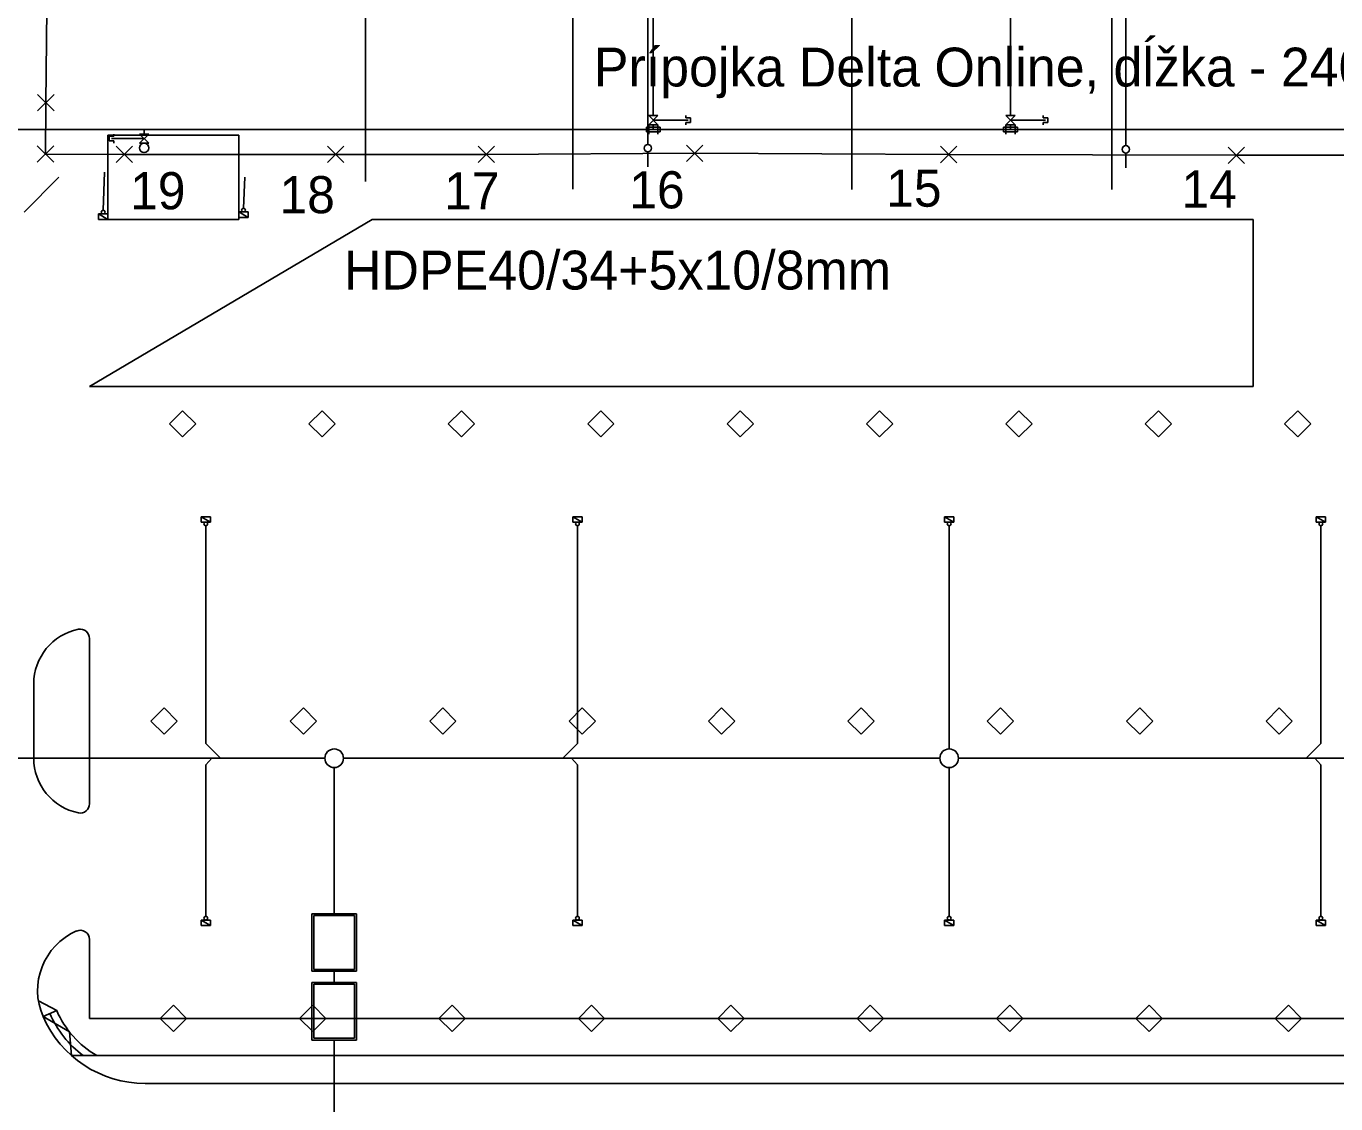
# Model space of a CAD drawing. Extents: x -263995 to -263575, y -1242437 to -1242140.
# Drawn here: x -263920.5 to -263850, y -1242302.6 to -1242244.6 of the extents above; entities that cross this region are included whole.
import ezdxf

# ---------------------------------------------------------------- set-up
doc = ezdxf.new("R2010")
doc.units = 0
for name, color, linetype in [('KFA_2D_SITUACIA_DSP', 7, 'Continuous'), ('KFA_BODY', 7, 'Continuous'), ('KFA_SO_63-3_PRELOZKA_DELTA_ONLINE_TRASA', 7, 'Continuous'), ('POPIS', 7, 'Continuous')]:
    doc.layers.add(name, color=color, linetype=linetype)

msp = doc.modelspace()

# ---------------------------------------------------------------- linework, layer by layer
at = {"layer": 'KFA_2D_SITUACIA_DSP'}
for p, q in [((-263887.043, -1242235.757), (-263887.043, -1242250.954)), ((-263886.743, -1242249.39), (-263886.743, -1242235.757)), ((-263867.518, -1242249.39), (-263867.518, -1242235.757)), ((-263861.318, -1242235.757), (-263861.321, -1242251.015)), ((-263902.238, -1242240.168), (-263902.238, -1242252.949)), ((-263891.068, -1242241.132), (-263891.068, -1242253.353)), ((-263876.068, -1242241.132), (-263876.068, -1242253.37)), ((-263862.068, -1242241.132), (-263862.068, -1242253.368)), ((-263886.493, -1242249.39), (-263886.993, -1242249.39)), ((-263886.993, -1242249.89), (-263886.493, -1242249.39)), ((-263886.993, -1242249.39), (-263886.493, -1242249.89)), ((-263886.493, -1242249.89), (-263886.993, -1242249.89)), ((-263886.993, -1242249.89), (-263886.993, -1242250.39)), ((-263886.743, -1242249.64), (-263884.868, -1242249.64)), ((-263886.743, -1242250.14), (-263886.743, -1242249.89)), ((-263886.743, -1242249.89), (-263886.743, -1242250.14)), ((-263886.493, -1242249.89), (-263886.493, -1242250.39)), ((-263884.993, -1242249.515), (-263884.993, -1242249.39)), ((-263884.743, -1242249.515), (-263884.993, -1242249.515)), ((-263884.993, -1242249.765), (-263884.993, -1242249.89)), ((-263884.993, -1242249.765), (-263884.743, -1242249.765)), ((-263884.743, -1242249.765), (-263884.743, -1242249.515)), ((-263867.268, -1242249.39), (-263867.768, -1242249.39)), ((-263867.768, -1242249.89), (-263867.268, -1242249.39)), ((-263867.768, -1242249.39), (-263867.268, -1242249.89)), ((-263867.268, -1242249.89), (-263867.768, -1242249.89)), ((-263867.768, -1242249.89), (-263867.768, -1242250.39)), ((-263867.518, -1242249.64), (-263865.643, -1242249.64)), ((-263867.518, -1242250.14), (-263867.518, -1242249.89)), ((-263867.518, -1242249.89), (-263867.518, -1242250.14)), ((-263867.268, -1242249.89), (-263867.268, -1242250.39)), ((-263865.768, -1242249.515), (-263865.768, -1242249.39)), ((-263865.518, -1242249.515), (-263865.768, -1242249.515)), ((-263865.768, -1242249.765), (-263865.768, -1242249.89)), ((-263865.768, -1242249.765), (-263865.518, -1242249.765)), ((-263865.518, -1242249.765), (-263865.518, -1242249.515)), ((-263924.143, -1242250.14), (-263788.143, -1242250.14)), ((-263916.093, -1242254.982), (-263916.093, -1242250.458)), ((-263916.093, -1242250.458), (-263909.043, -1242250.458)), ((-263916.018, -1242250.515), (-263915.768, -1242250.515)), ((-263916.018, -1242250.765), (-263916.018, -1242250.515)), ((-263914.143, -1242250.64), (-263915.893, -1242250.64)), ((-263915.768, -1242250.515), (-263915.768, -1242250.39)), ((-263914.393, -1242250.39), (-263913.893, -1242250.89)), ((-263913.893, -1242250.39), (-263914.393, -1242250.39)), ((-263914.393, -1242250.89), (-263913.893, -1242250.39)), ((-263914.143, -1242250.14), (-263914.143, -1242250.39)), ((-263914.143, -1242250.14), (-263914.143, -1242250.39)), ((-263909.043, -1242250.458), (-263909.043, -1242254.982)), ((-263886.368, -1242250.015), (-263887.118, -1242250.015)), ((-263887.118, -1242250.015), (-263887.118, -1242250.265)), ((-263887.118, -1242250.265), (-263886.368, -1242250.265)), ((-263886.368, -1242250.265), (-263886.368, -1242250.015)), ((-263867.143, -1242250.015), (-263867.893, -1242250.015)), ((-263867.893, -1242250.015), (-263867.893, -1242250.265)), ((-263867.893, -1242250.265), (-263867.143, -1242250.265)), ((-263867.143, -1242250.265), (-263867.143, -1242250.015)), ((-263915.768, -1242250.765), (-263916.018, -1242250.765)), ((-263915.768, -1242250.89), (-263915.768, -1242250.765)), ((-263913.893, -1242250.89), (-263914.393, -1242250.89)), ((-263887.043, -1242251.353), (-263887.043, -1242252.153)), ((-263861.321, -1242251.415), (-263861.321, -1242252.215)), ((-263920.595, -1242254.592), (-263918.723, -1242252.72)), ((-263916.339, -1242254.492), (-263916.265, -1242252.443)), ((-263908.789, -1242254.387), (-263908.729, -1242252.715)), ((-263916.593, -1242254.692), (-263916.093, -1242254.692)), ((-263916.593, -1242254.982), (-263916.593, -1242254.692)), ((-263916.593, -1242254.692), (-263916.093, -1242254.982)), ((-263916.593, -1242254.692), (-263916.093, -1242254.982)), ((-263916.093, -1242254.692), (-263916.593, -1242254.692)), ((-263916.093, -1242254.692), (-263916.093, -1242254.982)), ((-263916.093, -1242254.982), (-263916.093, -1242254.692)), ((-263909.043, -1242254.587), (-263908.543, -1242254.587)), ((-263909.043, -1242254.877), (-263909.043, -1242254.587)), ((-263909.043, -1242254.587), (-263908.543, -1242254.877)), ((-263909.043, -1242254.587), (-263908.543, -1242254.877)), ((-263908.543, -1242254.587), (-263909.043, -1242254.587)), ((-263908.543, -1242254.877), (-263909.043, -1242254.877)), ((-263908.543, -1242254.587), (-263908.543, -1242254.877)), ((-263908.543, -1242254.877), (-263908.543, -1242254.587)), ((-263917.08, -1242263.982), (-263901.868, -1242254.982)), ((-263916.093, -1242254.982), (-263916.593, -1242254.982)), ((-263909.043, -1242254.982), (-263916.093, -1242254.982)), ((-263901.868, -1242254.982), (-263854.468, -1242254.985)), ((-263854.468, -1242254.985), (-263854.468, -1242263.985)), ((-263854.468, -1242263.985), (-263917.08, -1242263.982)), ((-263912.775, -1242265.986), (-263912.068, -1242265.279)), ((-263912.068, -1242265.279), (-263911.361, -1242265.986)), ((-263905.275, -1242265.986), (-263904.568, -1242265.279)), ((-263904.568, -1242265.279), (-263903.861, -1242265.986)), ((-263897.775, -1242265.986), (-263897.068, -1242265.279)), ((-263897.775, -1242265.986), (-263897.068, -1242265.279)), ((-263897.068, -1242265.279), (-263896.361, -1242265.986)), ((-263897.068, -1242265.279), (-263896.361, -1242265.986)), ((-263890.275, -1242265.986), (-263889.568, -1242265.279)), ((-263889.568, -1242265.279), (-263888.861, -1242265.986)), ((-263882.775, -1242265.986), (-263882.068, -1242265.279)), ((-263882.068, -1242265.279), (-263881.361, -1242265.986)), ((-263875.275, -1242265.986), (-263874.568, -1242265.279)), ((-263874.568, -1242265.279), (-263873.861, -1242265.986)), ((-263867.775, -1242265.986), (-263867.068, -1242265.279)), ((-263867.068, -1242265.279), (-263866.361, -1242265.986)), ((-263860.275, -1242265.986), (-263859.568, -1242265.279)), ((-263859.568, -1242265.279), (-263858.861, -1242265.986)), ((-263852.775, -1242265.986), (-263852.068, -1242265.279)), ((-263852.068, -1242265.279), (-263851.361, -1242265.986)), ((-263912.068, -1242266.693), (-263912.775, -1242265.986)), ((-263911.361, -1242265.986), (-263912.068, -1242266.693)), ((-263904.568, -1242266.693), (-263905.275, -1242265.986)), ((-263903.861, -1242265.986), (-263904.568, -1242266.693)), ((-263897.068, -1242266.693), (-263897.775, -1242265.986)), ((-263897.068, -1242266.693), (-263897.775, -1242265.986)), ((-263896.361, -1242265.986), (-263897.068, -1242266.693)), ((-263896.361, -1242265.986), (-263897.068, -1242266.693)), ((-263889.568, -1242266.693), (-263890.275, -1242265.986)), ((-263888.861, -1242265.986), (-263889.568, -1242266.693)), ((-263882.068, -1242266.693), (-263882.775, -1242265.986)), ((-263881.361, -1242265.986), (-263882.068, -1242266.693)), ((-263874.568, -1242266.693), (-263875.275, -1242265.986)), ((-263873.861, -1242265.986), (-263874.568, -1242266.693)), ((-263867.068, -1242266.693), (-263867.775, -1242265.986)), ((-263866.361, -1242265.986), (-263867.068, -1242266.693)), ((-263859.568, -1242266.693), (-263860.275, -1242265.986)), ((-263858.861, -1242265.986), (-263859.568, -1242266.693)), ((-263852.068, -1242266.693), (-263852.775, -1242265.986)), ((-263851.361, -1242265.986), (-263852.068, -1242266.693)), ((-263911.074, -1242270.983), (-263910.574, -1242270.983)), ((-263911.074, -1242271.273), (-263911.074, -1242270.983)), ((-263911.074, -1242270.983), (-263910.574, -1242271.273)), ((-263911.074, -1242270.983), (-263910.574, -1242271.273)), ((-263910.574, -1242270.983), (-263911.074, -1242270.983)), ((-263910.574, -1242270.983), (-263910.574, -1242271.273)), ((-263910.574, -1242271.273), (-263910.574, -1242270.983)), ((-263891.074, -1242270.983), (-263890.574, -1242270.983)), ((-263891.074, -1242271.273), (-263891.074, -1242270.983)), ((-263891.074, -1242270.983), (-263890.574, -1242271.273)), ((-263891.074, -1242270.983), (-263890.574, -1242271.273)), ((-263890.574, -1242270.983), (-263891.074, -1242270.983)), ((-263890.574, -1242270.983), (-263890.574, -1242271.273)), ((-263890.574, -1242271.273), (-263890.574, -1242270.983)), ((-263871.074, -1242270.983), (-263870.574, -1242270.983)), ((-263871.074, -1242271.273), (-263871.074, -1242270.983)), ((-263871.074, -1242270.983), (-263870.574, -1242271.273)), ((-263871.074, -1242270.983), (-263870.574, -1242271.273)), ((-263870.574, -1242270.983), (-263871.074, -1242270.983)), ((-263870.574, -1242270.983), (-263870.574, -1242271.273)), ((-263870.574, -1242271.273), (-263870.574, -1242270.983)), ((-263851.074, -1242270.983), (-263850.574, -1242270.983)), ((-263851.074, -1242271.273), (-263851.074, -1242270.983)), ((-263851.074, -1242270.983), (-263850.574, -1242271.273)), ((-263851.074, -1242270.983), (-263850.574, -1242271.273)), ((-263850.574, -1242270.983), (-263851.074, -1242270.983)), ((-263850.574, -1242270.983), (-263850.574, -1242271.273)), ((-263850.574, -1242271.273), (-263850.574, -1242270.983)), ((-263910.574, -1242271.273), (-263911.074, -1242271.273)), ((-263910.824, -1242271.473), (-263910.824, -1242283.187)), ((-263890.574, -1242271.273), (-263891.074, -1242271.273)), ((-263890.824, -1242271.473), (-263890.824, -1242283.187)), ((-263870.574, -1242271.273), (-263871.074, -1242271.273)), ((-263870.824, -1242271.473), (-263870.824, -1242283.482)), ((-263850.574, -1242271.273), (-263851.074, -1242271.273)), ((-263850.824, -1242271.473), (-263850.824, -1242283.187)), ((-263917.08, -1242286.432), (-263917.08, -1242277.533)), ((-263920.08, -1242279.982), (-263920.08, -1242283.982)), ((-263913.775, -1242281.982), (-263913.068, -1242281.275)), ((-263913.068, -1242281.275), (-263912.361, -1242281.982)), ((-263906.275, -1242281.982), (-263905.568, -1242281.275)), ((-263905.568, -1242281.275), (-263904.861, -1242281.982)), ((-263898.775, -1242281.982), (-263898.068, -1242281.275)), ((-263898.068, -1242281.275), (-263897.361, -1242281.982)), ((-263891.275, -1242281.982), (-263890.568, -1242281.275)), ((-263891.275, -1242281.982), (-263890.568, -1242281.275)), ((-263890.568, -1242281.275), (-263889.861, -1242281.982)), ((-263890.568, -1242281.275), (-263889.861, -1242281.982)), ((-263883.775, -1242281.982), (-263883.068, -1242281.275)), ((-263883.068, -1242281.275), (-263882.361, -1242281.982)), ((-263876.275, -1242281.982), (-263875.568, -1242281.275)), ((-263875.568, -1242281.275), (-263874.861, -1242281.982)), ((-263868.775, -1242281.982), (-263868.068, -1242281.275)), ((-263868.068, -1242281.275), (-263867.361, -1242281.982)), ((-263861.275, -1242281.982), (-263860.568, -1242281.275)), ((-263860.568, -1242281.275), (-263859.861, -1242281.982)), ((-263853.775, -1242281.982), (-263853.068, -1242281.275)), ((-263853.068, -1242281.275), (-263852.361, -1242281.982)), ((-263913.068, -1242282.689), (-263913.775, -1242281.982)), ((-263912.361, -1242281.982), (-263913.068, -1242282.689)), ((-263905.568, -1242282.689), (-263906.275, -1242281.982)), ((-263904.861, -1242281.982), (-263905.568, -1242282.689)), ((-263898.068, -1242282.689), (-263898.775, -1242281.982)), ((-263897.361, -1242281.982), (-263898.068, -1242282.689)), ((-263890.568, -1242282.689), (-263891.275, -1242281.982)), ((-263890.568, -1242282.689), (-263891.275, -1242281.982)), ((-263889.861, -1242281.982), (-263890.568, -1242282.689)), ((-263889.861, -1242281.982), (-263890.568, -1242282.689)), ((-263883.068, -1242282.689), (-263883.775, -1242281.982)), ((-263882.361, -1242281.982), (-263883.068, -1242282.689)), ((-263875.568, -1242282.689), (-263876.275, -1242281.982)), ((-263874.861, -1242281.982), (-263875.568, -1242282.689)), ((-263868.068, -1242282.689), (-263868.775, -1242281.982)), ((-263867.361, -1242281.982), (-263868.068, -1242282.689)), ((-263860.568, -1242282.689), (-263861.275, -1242281.982)), ((-263859.861, -1242281.982), (-263860.568, -1242282.689)), ((-263853.068, -1242282.689), (-263853.775, -1242281.982)), ((-263852.361, -1242281.982), (-263853.068, -1242282.689)), ((-263910.824, -1242283.187), (-263910.029, -1242283.982)), ((-263890.824, -1242283.187), (-263891.619, -1242283.982)), ((-263850.824, -1242283.187), (-263851.619, -1242283.982)), ((-263946.608, -1242283.982), (-263908.955, -1242283.982)), ((-263946.608, -1242283.982), (-263904.413, -1242283.982)), ((-263910.824, -1242284.343), (-263910.499, -1242283.982)), ((-263910.824, -1242292.492), (-263910.824, -1242284.343)), ((-263903.913, -1242284.482), (-263903.913, -1242292.347)), ((-263871.324, -1242283.982), (-263903.413, -1242283.982)), ((-263890.824, -1242284.343), (-263891.149, -1242283.982)), ((-263890.824, -1242292.492), (-263890.824, -1242284.343)), ((-263870.824, -1242292.492), (-263870.824, -1242284.482)), ((-263817.941, -1242283.982), (-263870.324, -1242283.982)), ((-263817.941, -1242283.982), (-263870.324, -1242283.982)), ((-263850.824, -1242284.343), (-263851.149, -1242283.982)), ((-263850.824, -1242292.492), (-263850.824, -1242284.343)), ((-263911.074, -1242292.692), (-263910.574, -1242292.692)), ((-263911.074, -1242292.982), (-263911.074, -1242292.692)), ((-263911.074, -1242292.692), (-263910.574, -1242292.982)), ((-263911.074, -1242292.692), (-263910.574, -1242292.982)), ((-263910.574, -1242292.692), (-263911.074, -1242292.692)), ((-263910.574, -1242292.692), (-263910.574, -1242292.982)), ((-263910.574, -1242292.982), (-263910.574, -1242292.692)), ((-263905.113, -1242292.347), (-263902.713, -1242292.347)), ((-263905.113, -1242295.447), (-263905.113, -1242292.347)), ((-263905.013, -1242292.447), (-263902.813, -1242292.447)), ((-263905.013, -1242295.347), (-263905.013, -1242292.447)), ((-263902.813, -1242292.447), (-263902.813, -1242295.347)), ((-263902.713, -1242292.347), (-263902.713, -1242295.447)), ((-263891.074, -1242292.693), (-263890.574, -1242292.693)), ((-263891.074, -1242292.983), (-263891.074, -1242292.693)), ((-263891.074, -1242292.693), (-263890.574, -1242292.983)), ((-263891.074, -1242292.693), (-263890.574, -1242292.983)), ((-263890.574, -1242292.693), (-263891.074, -1242292.693)), ((-263890.574, -1242292.693), (-263890.574, -1242292.983)), ((-263890.574, -1242292.983), (-263890.574, -1242292.693)), ((-263871.074, -1242292.693), (-263870.574, -1242292.693)), ((-263871.074, -1242292.983), (-263871.074, -1242292.693)), ((-263871.074, -1242292.693), (-263870.574, -1242292.983)), ((-263871.074, -1242292.693), (-263870.574, -1242292.983)), ((-263870.574, -1242292.693), (-263871.074, -1242292.693)), ((-263870.574, -1242292.693), (-263870.574, -1242292.983)), ((-263870.574, -1242292.983), (-263870.574, -1242292.693)), ((-263851.074, -1242292.693), (-263850.574, -1242292.693)), ((-263851.074, -1242292.983), (-263851.074, -1242292.693)), ((-263851.074, -1242292.693), (-263850.574, -1242292.983)), ((-263851.074, -1242292.693), (-263850.574, -1242292.983)), ((-263850.574, -1242292.693), (-263851.074, -1242292.693)), ((-263850.574, -1242292.693), (-263850.574, -1242292.983)), ((-263850.574, -1242292.983), (-263850.574, -1242292.693)), ((-263910.574, -1242292.982), (-263911.074, -1242292.982)), ((-263890.574, -1242292.983), (-263891.074, -1242292.983)), ((-263870.574, -1242292.983), (-263871.074, -1242292.983)), ((-263850.574, -1242292.983), (-263851.074, -1242292.983)), ((-263917.08, -1242293.737), (-263917.08, -1242297.982)), ((-263905.113, -1242295.447), (-263902.713, -1242295.447)), ((-263905.013, -1242295.347), (-263902.813, -1242295.347)), ((-263903.913, -1242295.447), (-263903.913, -1242296.047)), ((-263905.113, -1242299.147), (-263905.113, -1242296.047)), ((-263902.713, -1242296.047), (-263905.113, -1242296.047)), ((-263902.813, -1242296.147), (-263905.013, -1242296.147)), ((-263905.013, -1242299.047), (-263905.013, -1242296.147)), ((-263902.813, -1242296.147), (-263902.813, -1242299.047)), ((-263902.713, -1242296.047), (-263902.713, -1242299.147)), ((-263918.846, -1242297.562), (-263919.828, -1242297.035)), ((-263918.846, -1242297.562), (-263919.579, -1242297.882)), ((-263919.579, -1242297.882), (-263918.155, -1242298.713)), ((-263913.275, -1242297.982), (-263912.568, -1242297.275)), ((-263912.568, -1242297.275), (-263911.861, -1242297.982)), ((-263905.775, -1242297.982), (-263905.068, -1242297.275)), ((-263905.068, -1242297.275), (-263904.361, -1242297.982)), ((-263898.275, -1242297.982), (-263897.568, -1242297.275)), ((-263897.568, -1242297.275), (-263896.861, -1242297.982)), ((-263890.775, -1242297.982), (-263890.068, -1242297.275)), ((-263890.775, -1242297.982), (-263890.068, -1242297.275)), ((-263890.068, -1242297.275), (-263889.361, -1242297.982)), ((-263890.068, -1242297.275), (-263889.361, -1242297.982)), ((-263883.275, -1242297.982), (-263882.568, -1242297.275)), ((-263882.568, -1242297.275), (-263881.861, -1242297.982)), ((-263875.775, -1242297.982), (-263875.068, -1242297.275)), ((-263875.068, -1242297.275), (-263874.361, -1242297.982)), ((-263868.275, -1242297.982), (-263867.568, -1242297.275)), ((-263867.568, -1242297.275), (-263866.861, -1242297.982)), ((-263860.775, -1242297.982), (-263860.068, -1242297.275)), ((-263860.068, -1242297.275), (-263859.361, -1242297.982)), ((-263853.275, -1242297.982), (-263852.568, -1242297.275)), ((-263852.568, -1242297.275), (-263851.861, -1242297.982)), ((-263815.601, -1242297.982), (-263917.08, -1242297.982)), ((-263912.568, -1242298.689), (-263913.275, -1242297.982)), ((-263911.861, -1242297.982), (-263912.568, -1242298.689)), ((-263905.068, -1242298.689), (-263905.775, -1242297.982)), ((-263904.361, -1242297.982), (-263905.068, -1242298.689)), ((-263897.568, -1242298.689), (-263898.275, -1242297.982)), ((-263896.861, -1242297.982), (-263897.568, -1242298.689)), ((-263890.068, -1242298.689), (-263890.775, -1242297.982)), ((-263890.068, -1242298.689), (-263890.775, -1242297.982)), ((-263889.361, -1242297.982), (-263890.068, -1242298.689)), ((-263889.361, -1242297.982), (-263890.068, -1242298.689)), ((-263882.568, -1242298.689), (-263883.275, -1242297.982)), ((-263881.861, -1242297.982), (-263882.568, -1242298.689)), ((-263875.068, -1242298.689), (-263875.775, -1242297.982)), ((-263874.361, -1242297.982), (-263875.068, -1242298.689)), ((-263867.568, -1242298.689), (-263868.275, -1242297.982)), ((-263866.861, -1242297.982), (-263867.568, -1242298.689)), ((-263860.068, -1242298.689), (-263860.775, -1242297.982)), ((-263859.361, -1242297.982), (-263860.068, -1242298.689)), ((-263852.568, -1242298.689), (-263853.275, -1242297.982)), ((-263851.861, -1242297.982), (-263852.568, -1242298.689)), ((-263918.155, -1242298.713), (-263918.049, -1242299.982)), ((-263902.713, -1242299.147), (-263905.113, -1242299.147)), ((-263902.813, -1242299.047), (-263905.013, -1242299.047)), ((-263903.913, -1242299.147), (-263903.913, -1242303.647)), ((-263816.308, -1242299.982), (-263918.049, -1242299.982)), ((-263914.08, -1242301.482), (-263815.822, -1242301.482))]:
    msp.add_line(p, q, dxfattribs=at)
for centre, radius in [((-263914.143, -1242251.14), 0.25), ((-263887.036, -1242251.153), 0.2), ((-263861.321, -1242251.215), 0.2), ((-263916.343, -1242254.592), 0.1), ((-263908.793, -1242254.487), 0.1), ((-263910.824, -1242271.373), 0.1), ((-263890.824, -1242271.373), 0.1), ((-263870.824, -1242271.373), 0.1), ((-263850.824, -1242271.373), 0.1), ((-263903.913, -1242283.982), 0.5), ((-263870.824, -1242283.982), 0.5), ((-263910.824, -1242292.592), 0.1), ((-263890.824, -1242292.592), 0.1), ((-263870.824, -1242292.592), 0.1), ((-263850.824, -1242292.592), 0.1)]:
    msp.add_circle(centre, radius, dxfattribs=at)
for centre, radius, start, end in [((-263917.08, -1242279.982), 3, 101.53696, 180), ((-263917.58, -1242277.533), 0.5, 0, 101.53696), ((-263917.08, -1242283.982), 3, 180, 258.46304), ((-263917.58, -1242286.432), 0.5, 258.46304, 0), ((-263916.372, -1242296.482), 3.5, 113.75985, 203.57818), ((-263917.58, -1242293.737), 0.5, 0, 113.75985), ((-263914.08, -1242295.482), 6, 203.57818, 270), ((-263914.08, -1242295.482), 5.6, 203.57818, 233.47251), ((-263914.08, -1242295.482), 5.2, 203.57818, 239.92665)]:
    msp.add_arc(centre, radius, start, end, dxfattribs=at)
at = {"layer": 'KFA_BODY'}
for p, q in [((-263919.873, -1242249.148), (-263918.989, -1242248.264)), ((-263918.989, -1242249.148), (-263919.873, -1242248.264)), ((-263919.888, -1242251.911), (-263919.004, -1242251.027)), ((-263919.004, -1242251.911), (-263919.888, -1242251.027)), ((-263915.647, -1242251.927), (-263914.763, -1242251.043)), ((-263914.763, -1242251.927), (-263915.647, -1242251.043)), ((-263904.272, -1242251.932), (-263903.388, -1242251.048)), ((-263903.388, -1242251.932), (-263904.272, -1242251.048)), ((-263896.166, -1242251.932), (-263895.282, -1242251.048)), ((-263895.282, -1242251.932), (-263896.166, -1242251.048)), ((-263884.955, -1242251.867), (-263884.071, -1242250.983)), ((-263884.071, -1242251.867), (-263884.955, -1242250.983)), ((-263871.293, -1242251.935), (-263870.409, -1242251.051)), ((-263870.409, -1242251.935), (-263871.293, -1242251.051)), ((-263855.821, -1242251.975), (-263854.937, -1242251.091)), ((-263854.937, -1242251.975), (-263855.821, -1242251.091))]:
    msp.add_line(p, q, dxfattribs=at)
at = {"layer": 'KFA_SO_63-3_PRELOZKA_DELTA_ONLINE_TRASA'}
msp.add_line((-263919.446, -1242251.469), (-263919.431, -1242248.706), dxfattribs=at)
for points in [[(-263919.431, -1242248.706), (-263919.32, -1242238.606), (-263919.749, -1242196.637), (-263919.939, -1242195.319)], [(-263786.989, -1242253.251), (-263790.94, -1242251.155), (-263796.831, -1242251.282), (-263810.843, -1242251.019), (-263819.249, -1242251.729), (-263828.948, -1242251.353), (-263839.873, -1242251.52), (-263855.379, -1242251.533), (-263870.851, -1242251.493), (-263884.513, -1242251.425), (-263895.724, -1242251.49), (-263903.83, -1242251.49), (-263915.205, -1242251.485), (-263919.446, -1242251.469)]]:
    msp.add_lwpolyline(points, dxfattribs=at)

# ---------------------------------------------------------------- texts
at = {"layer": 'KFA_BODY'}
for s, p in [('19', (-263914.891, -1242254.442)), ('18', (-263906.854, -1242254.654)), ('17', (-263897.994, -1242254.447)), ('16', (-263888.033, -1242254.393)), ('15', (-263874.209, -1242254.302)), ('14', (-263858.318, -1242254.349))]:
    msp.add_text(s, height=2, dxfattribs=at).set_placement(p)
at = {"layer": 'POPIS'}
for s, p in [('Prípojka Delta Online, dĺžka - 240,52 m', (-263889.945, -1242247.833)), ('HDPE40/34+5x10/8mm', (-263903.39, -1242258.758))]:
    msp.add_text(s, height=2.09, dxfattribs=at).set_placement(p)

doc.saveas('drawing.dxf')
